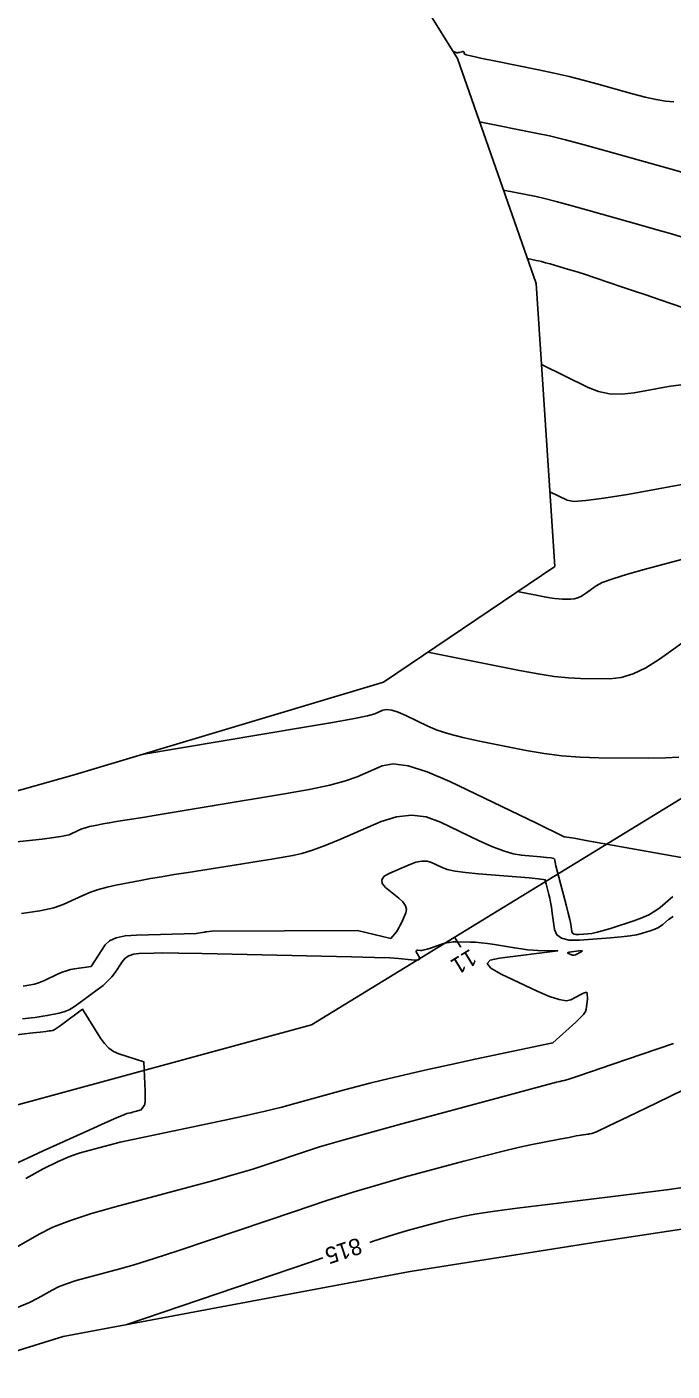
# Model space of a CAD drawing. Extents: x 1715724 to 1716561, y 394063 to 395906.
# Drawn here: x 1715932.8 to 1715987.4, y 394975.2 to 395089 of the extents above; entities that cross this region are included whole.
import ezdxf

# ---------------------------------------------------------------- set-up
doc = ezdxf.new("R2010")
doc.units = 0
for name, color, linetype in [('DT_X_Contour_Major', 7, 'Continuous'), ('DT_X_Contour_Minor', 7, 'Continuous'), ('DT_X_TIN_Hull', 7, 'Continuous'), ('GE_P_CL_10', 7, 'Continuous')]:
    doc.layers.add(name, color=color, linetype=linetype)

msp = doc.modelspace()

# ---------------------------------------------------------------- linework, layer by layer
at = {"layer": 'DT_X_Contour_Major'}
for points in [[(1715976.37, 395060.39), (1715980.33, 395058.44), (1715981.2, 395058.1), (1715982.14, 395057.91), (1715983.14, 395057.87), (1715984.21, 395057.99), (1715987.12, 395058.52), (1715988.17, 395058.66)], [(1715931.68, 395019.97), (1715934.11, 395020.23), (1715935.68, 395020.45), (1715936.4, 395020.61), (1715937.16, 395020.96), (1715937.46, 395021.09), (1715937.77, 395021.2), (1715938.11, 395021.29), (1715938.46, 395021.37), (1715939.42, 395021.55), (1715939.8, 395021.62), (1715940.24, 395021.69), (1715940.73, 395021.77), (1715942.79, 395022.1), (1715943.58, 395022.23), (1715944.79, 395022.42), (1715948.51, 395023.04), (1715954.62, 395024.06), (1715956.72, 395024.44), (1715958.45, 395024.81), (1715959.8, 395025.17), (1715960.78, 395025.51), (1715962.88, 395026.42), (1715963.83, 395026.59), (1715965.1, 395026.43), (1715966.69, 395025.93), (1715968.61, 395025.1), (1715975.95, 395021.57), (1715978.29, 395020.44), (1715978.31, 395020.44), (1715978.51, 395020.41), (1715979.13, 395020.3), (1715980.14, 395020.12), (1715981.57, 395019.86), (1715989.15, 395018.51)], [(1715988.51, 394990.79), (1715987.19, 394990.58), (1715983.55, 394990.13), (1715982.18, 394989.96), (1715980.8, 394989.79), (1715979.42, 394989.62), (1715978.03, 394989.45), (1715974.32, 394989), (1715973.06, 394988.85), (1715972.04, 394988.71), (1715971.27, 394988.6), (1715970.74, 394988.51), (1715969.68, 394988.3), (1715969.23, 394988.2), (1715968.67, 394988.07), (1715968, 394987.91), (1715967.23, 394987.7), (1715965.04, 394987.11), (1715963.9, 394986.78), (1715962.13, 394986.22), (1715961.85, 394986.12)], [(1715957.87, 394984.8), (1715956.73, 394984.41), (1715941.18, 394979.15)]]:
    msp.add_lwpolyline(points, dxfattribs=at)
at = {"layer": 'DT_X_Contour_Minor'}
for points in [[(1715968.91, 395086.86), (1715969.14, 395086.77), (1715969.19, 395086.76), (1715969.26, 395086.76), (1715969.33, 395086.77), (1715969.41, 395086.78), (1715969.64, 395086.85), (1715969.72, 395086.86), (1715969.77, 395086.86), (1715969.81, 395086.84), (1715969.82, 395086.8), (1715969.82, 395086.68), (1715970, 395086.6), (1715970.5, 395086.47), (1715971.35, 395086.28), (1715972.52, 395086.04), (1715976.12, 395085.31), (1715977.44, 395085.04), (1715978.71, 395084.75), (1715979.91, 395084.45), (1715981.07, 395084.13), (1715984.07, 395083.28), (1715985.14, 395083), (1715986.07, 395082.8), (1715986.88, 395082.67), (1715987.57, 395082.62)], [(1715971.14, 395080.93), (1715975.91, 395079.97), (1715977.05, 395079.72), (1715978.41, 395079.39), (1715980, 395078.97), (1715981.81, 395078.47), (1715986.95, 395077.02), (1715988.66, 395076.54)], [(1715973.16, 395075.14), (1715975.92, 395074.59), (1715976.64, 395074.42), (1715977.62, 395074.17), (1715978.87, 395073.84), (1715980.38, 395073.42), (1715984.77, 395072.18), (1715986.24, 395071.76), (1715987.38, 395071.43), (1715988.19, 395071.19)], [(1715975.18, 395069.35), (1715975.92, 395069.2), (1715976.11, 395069.16), (1715976.38, 395069.09), (1715976.71, 395069), (1715977.12, 395068.89), (1715978.29, 395068.55), (1715978.78, 395068.41), (1715979.39, 395068.22), (1715980.1, 395067.99), (1715980.91, 395067.72), (1715983.24, 395066.94), (1715984.17, 395066.63), (1715985.2, 395066.28), (1715986.33, 395065.9), (1715993.58, 395063.41)], [(1715977.08, 395049.62), (1715978.54, 395048.9), (1715979.1, 395048.81), (1715980.14, 395048.87), (1715981.66, 395049.07), (1715983.66, 395049.4), (1715989.65, 395050.48)], [(1715974.35, 395041.18), (1715976.62, 395040.73), (1715977.08, 395040.65), (1715977.49, 395040.58), (1715977.84, 395040.55), (1715978.14, 395040.53), (1715978.86, 395040.53), (1715979.15, 395040.55), (1715979.44, 395040.64), (1715979.76, 395040.8), (1715980.09, 395041.01), (1715981, 395041.66), (1715981.52, 395041.93), (1715982.4, 395042.26), (1715983.65, 395042.65), (1715985.25, 395043.1), (1715990.02, 395044.37)], [(1715966.75, 395036.05), (1715974.51, 395034.5), (1715976.08, 395034.21), (1715977.46, 395034), (1715978.67, 395033.87), (1715979.69, 395033.82), (1715982.16, 395033.8), (1715983.12, 395033.9), (1715984.14, 395034.21), (1715985.21, 395034.72), (1715986.35, 395035.45), (1715989.45, 395037.67)], [(1715942.56, 395027.39), (1715955.98, 395029.64), (1715958.52, 395030.07), (1715960.42, 395030.41), (1715961.66, 395030.66), (1715962.26, 395030.83), (1715962.96, 395031.13), (1715963.28, 395031.19), (1715963.71, 395031.13), (1715964.24, 395030.97), (1715964.89, 395030.69), (1715966.75, 395029.79), (1715967.54, 395029.46), (1715968.54, 395029.14), (1715969.73, 395028.83), (1715971.12, 395028.53), (1715975.09, 395027.74), (1715976.59, 395027.47), (1715978.11, 395027.28), (1715979.66, 395027.16), (1715981.23, 395027.12), (1715985.46, 395027.08), (1715986.89, 395027.1), (1715988, 395027.18)], [(1715932.36, 395013.93), (1715933.91, 395014.16), (1715935.09, 395014.42), (1715935.9, 395014.7), (1715937.55, 395015.47), (1715938.19, 395015.74), (1715938.87, 395015.98), (1715939.6, 395016.18), (1715940.36, 395016.34), (1715942.44, 395016.73), (1715943.27, 395016.89), (1715944.22, 395017.05), (1715945.29, 395017.23), (1715946.46, 395017.41), (1715950.91, 395018.11), (1715951.93, 395018.28), (1715952.81, 395018.42), (1715953.55, 395018.54), (1715955.34, 395018.84), (1715956.09, 395019.01), (1715957, 395019.29), (1715958.07, 395019.69), (1715959.3, 395020.2), (1715962.8, 395021.71), (1715964.1, 395022.13), (1715965.37, 395022.27), (1715966.61, 395022.12), (1715967.83, 395021.68), (1715971.05, 395020.13), (1715972.18, 395019.62), (1715973.16, 395019.24), (1715973.99, 395018.99), (1715974.67, 395018.87), (1715976.28, 395018.74), (1715976.81, 395018.69), (1715977.19, 395018.64), (1715977.42, 395018.59), (1715977.49, 395018.54), (1715977.5, 395018.42), (1715977.53, 395018.28), (1715977.6, 395017.96), (1715977.73, 395017.45), (1715978.45, 395014.67), (1715978.63, 395013.97), (1715978.77, 395013.42), (1715978.85, 395013.03), (1715978.9, 395012.81), (1715978.95, 395012.41), (1715979.01, 395012.28), (1715979.13, 395012.2), (1715979.31, 395012.15), (1715979.56, 395012.15), (1715980.31, 395012.21), (1715980.64, 395012.26), (1715981.08, 395012.36), (1715981.63, 395012.51), (1715982.29, 395012.71), (1715984.18, 395013.31), (1715984.86, 395013.56), (1715985.45, 395013.83), (1715985.97, 395014.13), (1715986.42, 395014.46), (1715987.5, 395015.39)], [(1715932.5, 395007.8), (1715932.98, 395007.87), (1715933.45, 395007.97), (1715933.89, 395008.11), (1715934.31, 395008.28), (1715935.41, 395008.8), (1715935.81, 395008.97), (1715936.18, 395009.1), (1715936.52, 395009.2), (1715936.84, 395009.26), (1715938.25, 395009.45), (1715939.44, 395011.28), (1715939.8, 395011.62), (1715940.37, 395011.88), (1715941.14, 395012.04), (1715942.11, 395012.11), (1715947.15, 395012.24), (1715947.85, 395012.37), (1715947.94, 395012.38), (1715948.03, 395012.4), (1715948.44, 395012.46), (1715960.79, 395012.49), (1715963.61, 395011.83), (1715964.09, 395012.39), (1715964.19, 395012.53), (1715964.3, 395012.72), (1715964.42, 395012.94), (1715964.55, 395013.21), (1715964.89, 395013.99), (1715964.95, 395014.29), (1715964.87, 395014.6), (1715964.65, 395014.92), (1715964.3, 395015.25), (1715963.18, 395016.15), (1715962.89, 395016.48), (1715962.85, 395016.79), (1715963.07, 395017.09), (1715963.55, 395017.36), (1715965.17, 395018.06), (1715965.74, 395018.27), (1715966.25, 395018.37), (1715966.69, 395018.37), (1715967.06, 395018.26), (1715967.96, 395017.83), (1715968.4, 395017.67), (1715969.06, 395017.53), (1715969.95, 395017.41), (1715971.05, 395017.3), (1715974.27, 395017.04), (1715975.33, 395016.95), (1715976.08, 395016.88), (1715976.54, 395016.83), (1715976.69, 395016.8), (1715976.69, 395016.76), (1715976.7, 395016.72), (1715976.72, 395016.61), (1715976.76, 395016.45), (1715976.82, 395016.22), (1715977, 395015.54), (1715977.07, 395015.25), (1715977.14, 395014.89), (1715977.21, 395014.47), (1715977.28, 395013.98), (1715977.48, 395012.59), (1715977.67, 395012.14), (1715978.08, 395011.84), (1715978.73, 395011.69), (1715979.6, 395011.69), (1715982.23, 395011.89), (1715983.13, 395011.97), (1715983.87, 395012.05), (1715984.43, 395012.14), (1715984.83, 395012.24), (1715985.66, 395012.5), (1715985.96, 395012.61), (1715986.22, 395012.73), (1715986.45, 395012.86), (1715986.65, 395013.01), (1715987.12, 395013.42), (1715987.53, 395013.69)], [(1715932.44, 395005.02), (1715933.21, 395005.1), (1715933.51, 395005.14), (1715933.83, 395005.19), (1715934.17, 395005.25), (1715934.54, 395005.31), (1715935.56, 395005.5), (1715935.95, 395005.61), (1715936.39, 395005.8), (1715936.86, 395006.08), (1715937.37, 395006.43), (1715938.78, 395007.47), (1715939.27, 395007.86), (1715939.68, 395008.23), (1715940.02, 395008.59), (1715940.28, 395008.94), (1715940.88, 395009.85), (1715941.14, 395010.15), (1715941.46, 395010.37), (1715941.84, 395010.51), (1715942.29, 395010.56), (1715943.56, 395010.59), (1715944.33, 395010.6), (1715945.69, 395010.58), (1715947.65, 395010.55), (1715950.19, 395010.5), (1715957.76, 395010.34), (1715960.3, 395010.28), (1715962.23, 395010.23), (1715963.55, 395010.18), (1715964.27, 395010.13), (1715965.38, 395010.02), (1715965.74, 395010), (1715965.97, 395010.03), (1715966.07, 395010.1), (1715966.05, 395010.21), (1715965.84, 395010.57), (1715965.78, 395010.69), (1715965.77, 395010.77), (1715965.8, 395010.81), (1715965.87, 395010.83), (1715966.14, 395010.81), (1715966.26, 395010.82), (1715966.45, 395010.86), (1715966.69, 395010.92), (1715966.99, 395011.02), (1715967.86, 395011.32), (1715968.19, 395011.42), (1715968.55, 395011.49), (1715968.92, 395011.53), (1715969.3, 395011.54), (1715970.36, 395011.52), (1715970.78, 395011.51), (1715971.27, 395011.47), (1715971.81, 395011.4), (1715972.4, 395011.31), (1715974.08, 395011.03), (1715974.67, 395010.94), (1715975.2, 395010.87), (1715975.66, 395010.83), (1715976.06, 395010.81), (1715977.75, 395010.78), (1715972.81, 395010.16), (1715972.02, 395009.98), (1715971.79, 395009.7), (1715972.1, 395009.31), (1715972.97, 395008.82), (1715976.01, 395007.38), (1715977.04, 395006.93), (1715977.86, 395006.66), (1715978.47, 395006.56), (1715978.87, 395006.63), (1715979.66, 395007.07), (1715979.92, 395007.21), (1715980.1, 395007.27), (1715980.21, 395007.26), (1715980.25, 395007.19), (1715980.26, 395006.68), (1715980.16, 395005.86), (1715980.09, 395005.65), (1715979.92, 395005.4), (1715979.65, 395005.1), (1715979.28, 395004.75), (1715977.34, 395002.99), (1715970.62, 395001.59), (1715969.23, 395001.29), (1715967.94, 395001.01), (1715966.75, 395000.75), (1715965.66, 395000.49), (1715962.89, 394999.83), (1715961.84, 394999.58), (1715960.77, 394999.31), (1715959.69, 394999.02), (1715958.58, 394998.72), (1715955.61, 394997.89), (1715954.4, 394997.57), (1715952.99, 394997.22), (1715951.38, 394996.85), (1715949.58, 394996.47), (1715940.7, 394994.6), (1715937.33, 394993.7), (1715936.5, 394993.42), (1715935.46, 394992.96), (1715934.2, 394992.33), (1715932.73, 394991.53)], [(1715978.65, 395010.56), (1715978.59, 395010.6), (1715978.62, 395010.64), (1715978.73, 395010.68), (1715978.92, 395010.71), (1715979.53, 395010.79), (1715979.71, 395010.8), (1715979.81, 395010.79), (1715979.81, 395010.76), (1715979.72, 395010.69), (1715979.37, 395010.5), (1715979.24, 395010.44), (1715979.12, 395010.41), (1715979.01, 395010.41), (1715978.91, 395010.44), (1715978.65, 395010.56)], [(1715931.45, 395003.62), (1715933.32, 395003.84), (1715933.95, 395003.91), (1715934.41, 395003.96), (1715934.71, 395004), (1715934.85, 395004.02), (1715935.02, 395004.05), (1715935.13, 395004.1), (1715935.3, 395004.2), (1715935.54, 395004.37), (1715935.86, 395004.6), (1715937.53, 395005.84), (1715939.04, 395003.4), (1715939.38, 395002.93), (1715939.75, 395002.55), (1715940.16, 395002.26), (1715940.6, 395002.07), (1715942.73, 395001.39), (1715942.82, 394998.91), (1715942.83, 394998.43), (1715942.82, 394998.07), (1715942.79, 394997.82), (1715942.75, 394997.69), (1715942.5, 394997.32), (1715941.97, 394997.18), (1715941.86, 394997.15), (1715941.76, 394997.12), (1715941.65, 394997.09), (1715941.55, 394997.07), (1715941.28, 394997.02), (1715941.01, 394996.91), (1715940.4, 394996.65), (1715939.44, 394996.23), (1715938.14, 394995.64), (1715934.21, 394993.86), (1715932.86, 394993.25), (1715931.76, 394992.73)], [(1715987.54, 395002.93), (1715982.33, 395001.16), (1715980.61, 395000.58), (1715979.36, 395000.16), (1715978.6, 394999.91), (1715978.3, 394999.81), (1715978.15, 394999.78), (1715978.09, 394999.77), (1715978.03, 394999.76), (1715977.97, 394999.74), (1715977.92, 394999.73), (1715977.64, 394999.67), (1715964.24, 394996.07), (1715961.59, 394995.34), (1715959.37, 394994.72), (1715957.58, 394994.19), (1715956.23, 394993.75), (1715953.2, 394992.73), (1715951.93, 394992.32), (1715950.37, 394991.85), (1715948.54, 394991.33), (1715946.42, 394990.76), (1715940.4, 394989.16), (1715938.3, 394988.56), (1715936.51, 394987.97), (1715935.02, 394987.39), (1715933.85, 394986.81), (1715931.14, 394985.27)], [(1715993.09, 395001.31), (1715986.07, 394997.9), (1715983.75, 394996.77), (1715982.08, 394995.97), (1715981.04, 394995.48), (1715980.65, 394995.32), (1715980.43, 394995.29), (1715980.36, 394995.28), (1715980.28, 394995.27), (1715980.12, 394995.25), (1715979.9, 394995.22), (1715979.72, 394995.19), (1715979.32, 394995.12), (1715978.72, 394995), (1715977.9, 394994.84), (1715975.45, 394994.36), (1715974.41, 394994.14), (1715973.12, 394993.83), (1715971.59, 394993.45), (1715969.81, 394992.98), (1715964.74, 394991.62), (1715962.74, 394991.05), (1715960.53, 394990.39), (1715958.11, 394989.62), (1715955.48, 394988.74), (1715948.19, 394986.28), (1715945.67, 394985.43), (1715943.58, 394984.75), (1715941.91, 394984.23), (1715940.68, 394983.88), (1715937.94, 394983.15), (1715936.99, 394982.88), (1715936.17, 394982.61), (1715935.5, 394982.35), (1715934.97, 394982.08), (1715933.74, 394981.39), (1715933.04, 394981.04), (1715931.87, 394980.54)]]:
    msp.add_lwpolyline(points, dxfattribs=at)
at = {"layer": 'DT_X_TIN_Hull'}
for points in [[(1715955.44, 395108.47), (1715969.27, 395086.28), (1715975.92, 395067.23), (1715977.5, 395043.31), (1715963, 395033.52), (1715936.83, 395025.68), (1715910.58, 395018.28)], [(1715915.4, 394971.82), (1715935.9, 394978.16), (1715965.26, 394983.66), (1715981.17, 394986.17), (1715995.31, 394988.32), (1716023.7, 394993.38), (1716039.08, 394962.62), (1716053.65, 394961.61), (1716061.25, 394947.63), (1716073.72, 394919.83)]]:
    msp.add_lwpolyline(points, dxfattribs=at)
at = {"layer": 'GE_P_CL_10'}
for p, q in [((1715997.39, 395029.31), (1715956.92, 395004.53)), ((1715969.02, 395011.94), (1715969.55, 395011.09)), ((1715956.92, 395004.53), (1715907.41, 394991.08))]:
    msp.add_line(p, q, dxfattribs=at)

# ---------------------------------------------------------------- texts
at = {"layer": 'DT_X_Contour_Major'}
msp.add_text('815', height=1.4, rotation=198.407, dxfattribs=at).set_placement((1715960.89, 394986.55))
at = {"layer": 'GE_P_CL_10'}
msp.add_text('11', height=1.4, rotation=211.4731, dxfattribs=at).set_placement((1715970.34, 395010.99))

doc.saveas('drawing.dxf')
